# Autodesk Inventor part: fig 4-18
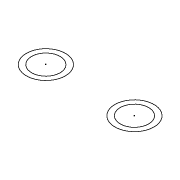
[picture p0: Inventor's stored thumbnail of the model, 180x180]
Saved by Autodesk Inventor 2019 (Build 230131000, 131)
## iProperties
Created: 2005-02
Part Number: fig 4-18
Document SubType Name: Modeling
Designer: CADCIM
Manufacturer: Standard
Standards Organization: Custom
Density: 1 g/cm^3
Material: Generic
Appearance: Default
Author: CADCIM
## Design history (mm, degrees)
sketch "Sketch1"
  geometry: C1 r 7.935 at (-23.563, 7.599); C2 r 7.935 at (12.452, 7.599); C3 r 5.782 at (-23.563, 7.599); C4 r 5.782 at (12.452, 7.599)
  constraints: 4 centre point, 1 coincident, 1 equal radius, 1 other
